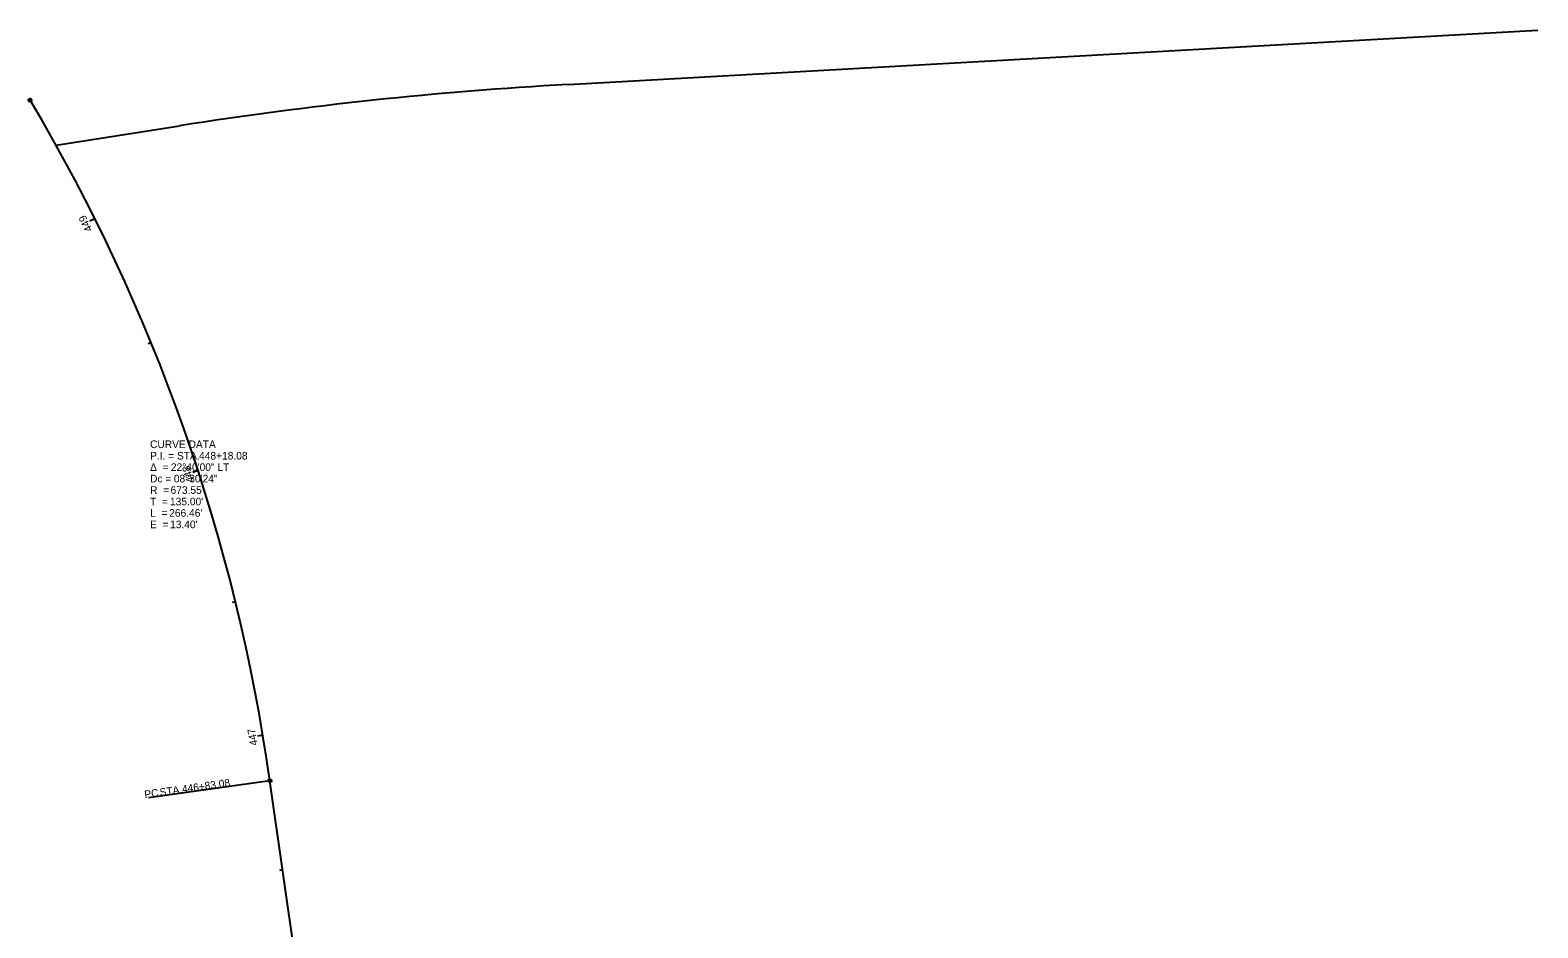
# Model space of a CAD drawing. Extents: x 124376 to 127490, y 510907 to 515083.
# Drawn here: x 126936 to 127490, y 511950 to 512279 of the extents above; entities that cross this region are included whole.
import ezdxf

# ---------------------------------------------------------------- set-up
doc = ezdxf.new("R2010")
doc.units = 0
for name, color, linetype in [('Default', 7, 'Continuous'), ('GE_X_Alignment', 7, 'Continuous'), ('RW_X_CL', 7, 'Continuous'), ('RW_X_CL_100_Cardinal_Points', 7, 'Continuous'), ('RW_X_CL_100_Curve_Data', 7, 'Continuous'), ('RW_X_CL_100_Stations', 7, 'Continuous')]:
    doc.layers.add(name, color=color, linetype=linetype)

msp = doc.modelspace()

# ---------------------------------------------------------------- linework, layer by layer
at = {"layer": 'Default'}
msp.add_line((127064.82, 511719.28), (127024.38, 512004), dxfattribs=at)
for centre, radius, start, end in [((127213.81, 510829.3), 1432.39, 93.20256, 98.94008), ((126357.53, 511909.29), 673.55, 8.08366, 30.75033)]:
    msp.add_arc(centre, radius, start, end, dxfattribs=at)
at = {"layer": 'GE_X_Alignment'}
for p, q in [((127133.79, 512259.46), (127489.75, 512279.38)), ((126945.88, 512237.17), (126991.21, 512244.3))]:
    msp.add_line(p, q, dxfattribs=at)
msp.add_arc((127213.81, 510829.3), 1432.39, 93.20256, 98.94008, dxfattribs=at)
at = {"layer": 'RW_X_CL'}
msp.add_line((127064.82, 511719.28), (127024.38, 512004), dxfattribs=at)
msp.add_arc((126357.53, 511909.29), 673.55, 8.08366, 30.75033, dxfattribs=at)
at = {"layer": 'RW_X_CL_100_Cardinal_Points'}
msp.add_line((127024.38, 512004), (126979.83, 511997.68), dxfattribs=at)
for centre in [(126936.37, 512253.67), (127024.38, 512004)]:
    msp.add_circle(centre, 0.6, dxfattribs=at)
at = {"layer": 'RW_X_CL_100_Stations'}
for p, q in [((126960.11, 512210.21), (126958.33, 512209.31)), ((126980.77, 512164.69), (126979.66, 512164.23)), ((126998, 512117.76), (126996.1, 512117.14)), ((127011.7, 512069.68), (127010.53, 512069.4)), ((127021.79, 512020.72), (127019.82, 512020.39)), ((127029.03, 511971.25), (127027.84, 511971.08))]:
    msp.add_line(p, q, dxfattribs=at)

# ---------------------------------------------------------------- texts
at = {"layer": 'RW_X_CL_100_Cardinal_Points'}
for s, p in [('446+83.08', (126992.3, 511999.48)), ('PC', (126978.51, 511997.53)), (' STA. ', (126983.07, 511998.17))]:
    msp.add_text(s, height=2.8, rotation=8.0837, dxfattribs=at).set_placement(p)
at = {"layer": 'RW_X_CL_100_Curve_Data'}
for s, p in [('CURVE DATA', (126980.38, 512126.04)), ('Δ  = ', (126980.38, 512117.64)), ('P.I. = STA. ', (126980.38, 512121.84)), ('22°40\'00" LT', (126988.02, 512117.64)), ('448+18.08', (126998.37, 512121.84)), ('Dc = ', (126980.38, 512113.44)), ('08°30\'24"', (126989.12, 512113.44)), ('R  = ', (126980.38, 512109.24)), ("673.55'", (126987.91, 512109.24)), ('T  = ', (126980.38, 512105.04)), ('L  = ', (126980.38, 512100.84)), ("266.46'", (126987.41, 512100.84)), ("135.00'", (126987.7, 512105.04)), ('E  = ', (126980.38, 512096.64)), ("13.40'", (126987.72, 512096.64))]:
    msp.add_text(s, height=2.8, dxfattribs=at).set_placement(p)
at = {"layer": 'RW_X_CL_100_Stations'}
for s, rotation, p in [('449', 116.5362, (126959.32, 512206.2)), ('448', 108.0296, (126996.63, 512113.89)), ('447', 99.523, (127019.86, 512017.11))]:
    msp.add_text(s, height=2.8, rotation=rotation, dxfattribs=at).set_placement(p)

doc.saveas('drawing.dxf')
